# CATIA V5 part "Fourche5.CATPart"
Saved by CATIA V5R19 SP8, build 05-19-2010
Part number: Fourche5
Bounding box of the stored display mesh (mm): x -128 to -123, y 0.294 to 8.873, z -38.704 to 15.578
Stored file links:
  G:\EU_thinkMotion\CFAO_2010\MMS_groupe2\MMS_groupe2\A reprendre\jcauchy\Fourche5.CATPart
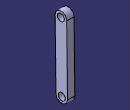
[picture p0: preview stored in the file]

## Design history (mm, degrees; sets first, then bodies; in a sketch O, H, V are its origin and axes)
Parameters
  Largeurfourche_fourche5 = 8 mm
  Rayonfixation_fourche5 = 2.5 mm
  Hauteurfourche_fourche5 = 5 mm
  separationfixation_fourche5 = 120 mm
  separationroue_fourche5 = 64 mm
Set1
  DatumSurface1
  Sketch1 on face of DatumSurface1, origin (-123, 0, 0), H (0, -1, 0), V (0, 0, 1)
    line L1 (-8.2938, 11.8086) -> (-8.8729, -34.8355)
    point P2 (-8.8729, -34.8355)
    arc A1 centre (-4.2941, 11.7589) radius 4 from (-0.2944, 11.7092) to (-8.2938, 11.8086) ccw
    point P3 (-4.2941, 11.7589)
    line L2 (-0.2944, 11.7092) -> (-0.8735, -34.9348)
    point P5 (-0.8735, -34.9348)
    arc A2 centre (-4.8732, -34.8851) radius 4 from (-8.8729, -34.8355) to (-0.8735, -34.9348) ccw
    point P6 (-4.8732, -34.8851)
    point P7 (-0.8735, -34.9348)
    point P8 (-8.8729, -34.8355)
    distance L1 L2 = 8 {= Largeurfourche_fourche5}
    distance P3 P6 = 46.6476 {= sqrt((separationroue_fourche5 -(separationfixation_fourche5 -(separationroue_fourche5 +separationroue_fourche5 /2)))*(separationroue_fourche5 -(separationfixation_fourche5 -(separationroue_fourche5 +separationroue_fourche5 /2)))+(separationfixation_fourche5 -(separationroue_fourche5 +separationroue_fourche5 /2))*(separationfixation_fourche5 -(separationroue_fourche5 +separationroue_fourche5 /2))*tan(45deg)*tan(45deg))}
    parallelism: L2 L1
    tangency: A1 L2, L1 A1, A2 L2, A2 L1
    coincidence: P7 L2, P7 P5, P8 P2
  Point1: stored without definition
  DatumPoint1
Body1 (main body)
  Pad1: profile Sketch1, direction (-1, 0, 0), length 5 {= Hauteurfourche_fourche5}
  Sketch2 on start face of Pad1, origin (-123, 5.5197, -33.4101), H (0, 1, 0), V (0, 0, 1)
    point P1 (-0.6465, -1.475)
    reference projected line E1 (-4.6462, -1.5247) -> (-5.4234, 61.0662) from edge [start face of Pad1 | face of Pad1 from Sketch1.L2]
    reference projected arc E2 centre (-0.6465, -1.475) radius 4 from (-4.6462, -1.5247) to (3.3532, -1.4254) ccw from edge [start face of Pad1 | face of Pad1 from Sketch1.A2]
    distance P1 E1 = 4 {= Largeurfourche_fourche5 /2}
    distance P1 E2 = 4 {= Largeurfourche_fourche5 /2}
  Hole1: placed by Sketch2, at (-123, 4.8732, -34.8851) direction (-1, 0, 0), diameter 5 {= Rayonfixation_fourche5 *2}, through (limit type 6)
  Sketch3 on start face of Pad1, origin (-123, 3.14, 26.2411), H (0, 1, 0), V (0, 0, 1)
    point P1 (1.154, -14.4822)
    reference projected arc E1 centre (1.154, -14.4822) radius 4 from (5.1537, -14.4325) to (-2.8457, -14.5318) ccw from edge [start face of Pad1 | face of Pad1 from Sketch1.A1]
    distance P1 E1 = 4
  Hole2: placed by Sketch3, at (-123, 4.2941, 11.7589) direction (-1, 0, 0), diameter 5 {= Rayonfixation_fourche5 *2}, through (limit type 6)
